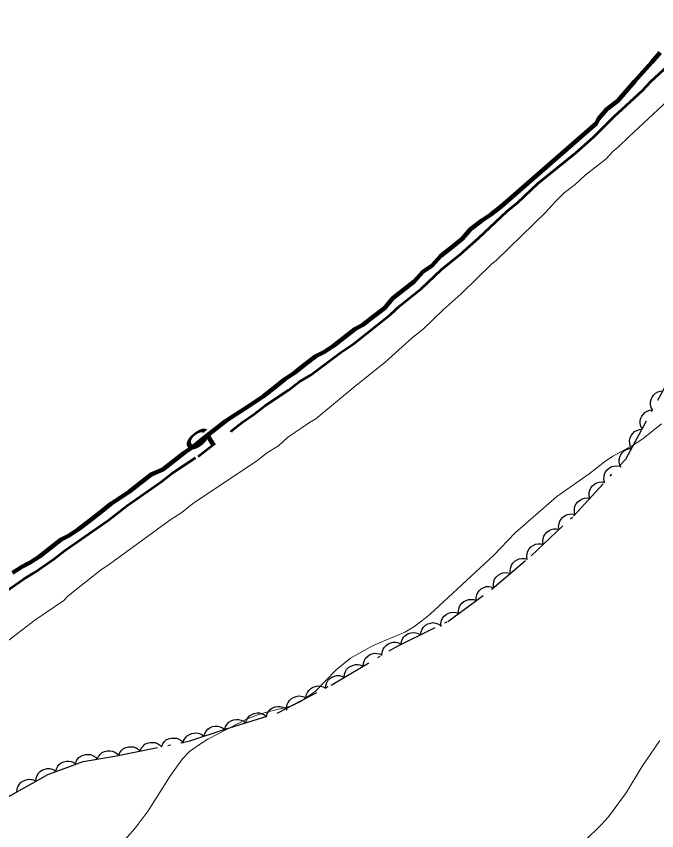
# Model space of a CAD drawing. Extents: x 355726 to 357533, y 5103782 to 5105258.
# Drawn here: x 355865.5 to 355909.5, y 5104531.6 to 5104587.5 of the extents above; entities that cross this region are included whole.
import ezdxf
from ezdxf.enums import TextEntityAlignment as Align

# ---------------------------------------------------------------- set-up
doc = ezdxf.new("R2010")
doc.units = 0
doc.header["$LTSCALE"] = 0.6
for name, pattern in [('DASH_DOUBLE_DOT', [9.2, 5, -1.2, 0.3, -1.2, 0.3, -1.2]), ('DOT_DASHED', [7.7, 5, -1.2, 0.3, -1.2]), ('LONG_DASHED', [7.5, 6, -1.5])]:
    doc.linetypes.add(name, pattern=pattern)
for name, color, linetype, lineweight in [('1', 7, 'LONG_DASHED', 53), ('2', 7, 'LONG_DASHED', 13), ('4', 7, 'DASH_DOUBLE_DOT', 53), ('44', 7, 'Continuous', 25)]:
    doc.layers.add(name, color=color, linetype=linetype, lineweight=lineweight)

msp = doc.modelspace()

# ---------------------------------------------------------------- linework, layer by layer
at = {"layer": '1', "linetype": 'Continuous'}
for points in [[(355880.28, 5104559.03), (355880.32, 5104559.11), (355881.05, 5104559.69), (355881.87, 5104560.23), (355882.6, 5104560.8), (355884.22, 5104561.88), (355884.96, 5104562.46), (355885.72, 5104562.92), (355887.84, 5104564.5), (355888.65, 5104565.04), (355891.22, 5104567.07), (355891.88, 5104567.69), (355893.35, 5104568.85), (355894.71, 5104570.17), (355896.02, 5104571.22), (355897.25, 5104572.31), (355899.23, 5104574.18), (355899.97, 5104574.76), (355901.33, 5104576.08), (355903.94, 5104578.18), (355905.18, 5104579.28), (355906.58, 5104580.67), (355908.52, 5104582.46), (355909.06, 5104583.05), (355913.95, 5104587.55)], [(355841.16, 5104531.16), (355844.5, 5104533.84), (355845.27, 5104534.3), (355847.39, 5104535.88), (355848.89, 5104536.92), (355850.07, 5104537.94), (355851.58, 5104538.98), (355852.31, 5104539.56), (355855.27, 5104541.56), (355856, 5104542.14), (355857.42, 5104543.03), (355857.82, 5104543.2), (355863.78, 5104547.28), (355864.51, 5104547.86), (355866.02, 5104548.9), (355866.78, 5104549.36), (355868.12, 5104550.3), (355868.86, 5104550.88), (355871.86, 5104552.96), (355873.12, 5104553.93), (355875.48, 5104555.58), (355876.21, 5104556.16), (355877.84, 5104557.23)]]:
    msp.add_lwpolyline(points, dxfattribs=at)
at = {"layer": '2', "linetype": 'Continuous'}
for points in [[(355865.02, 5104544.71), (355866.81, 5104546.08), (355868.8, 5104547.44), (355869.09, 5104547.77), (355871.29, 5104549.5), (355871.94, 5104549.93), (355876.08, 5104552.95), (355876.89, 5104553.49), (355877.63, 5104554.07), (355882.04, 5104557.04), (355882.78, 5104557.61), (355883.54, 5104558.07), (355884.16, 5104558.62), (355885.66, 5104559.66), (355886.1, 5104559.91), (355888.8, 5104562.16), (355890.84, 5104563.79), (355892.73, 5104565.5), (355893.47, 5104566.08), (355894.83, 5104567.4), (355896.06, 5104568.49), (355898.12, 5104570.51), (355898.49, 5104570.8), (355901.91, 5104574.13), (355902.49, 5104574.79), (355903.15, 5104575.42), (355903.89, 5104575.99), (355904.55, 5104576.62), (355906.02, 5104577.77), (355906.51, 5104578.29), (355906.88, 5104578.58), (355907.58, 5104579.28), (355912.56, 5104583.92)], [(355907.84, 5104558.09), (355908.55, 5104558.54), (355909.83, 5104559.58)], [(355872.63, 5104530.63), (355873.68, 5104531.8), (355874.58, 5104533.01), (355876.11, 5104535.42), (355876.93, 5104536.57), (355877.43, 5104537.07), (355878.04, 5104537.51), (355878.67, 5104537.92), (355881.34, 5104539.29), (355881.97, 5104539.55), (355882.62, 5104539.75), (355884.47, 5104540.2), (355885.02, 5104540.48), (355886.07, 5104541.22), (355887.5, 5104542.67), (355888.47, 5104543.47), (355889.98, 5104544.32), (355892.26, 5104545.3), (355892.82, 5104545.63), (355893.38, 5104546.04), (355893.94, 5104546.51), (355898.29, 5104550.53), (355899.78, 5104552.08), (355902.08, 5104554.11), (355902.64, 5104554.57), (355904.85, 5104556.13), (355905.9, 5104556.97), (355906.48, 5104557.36), (355907.84, 5104558.09)]]:
    msp.add_lwpolyline(points, dxfattribs=at)
at = {"layer": '2'}
msp.add_lwpolyline([(355904.56, 5104530.95), (355905.69, 5104532.04), (355906.18, 5104532.59), (355907.4, 5104534.24), (355908.48, 5104536.01), (355909.7, 5104537.84)], dxfattribs=at)
at = {"layer": '4', "linetype": 'Continuous', "lineweight": 90}
msp.add_lwpolyline([(355909.73, 5104585.07), (355909.15, 5104584.41), (355908.57, 5104583.74), (355907.98, 5104583.08), (355907.4, 5104582.41), (355906.82, 5104581.75), (355906.08, 5104581.17), (355905.5, 5104580.5), (355905.33, 5104580.2), (355898.84, 5104574.52), (355898.1, 5104573.94), (355897.46, 5104573.51), (355896.72, 5104572.93), (355896.14, 5104572.26), (355895.4, 5104571.68), (355894.67, 5104571.1), (355894.08, 5104570.44), (355893.44, 5104570.01), (355892.85, 5104569.34), (355892.12, 5104568.77), (355891.38, 5104568.19), (355890.8, 5104567.52), (355890.06, 5104566.94), (355889.33, 5104566.36), (355888.77, 5104566.08), (355888.03, 5104565.5), (355887.3, 5104564.92), (355886.65, 5104564.5), (355886.09, 5104564.22), (355885.35, 5104563.64), (355884.62, 5104563.06), (355883.97, 5104562.63), (355883.23, 5104562.05), (355882.5, 5104561.47), (355881.85, 5104561.04), (355881.2, 5104560.61), (355880.55, 5104560.18), (355879.9, 5104559.76), (355879.17, 5104559.18), (355878.43, 5104558.6), (355877.7, 5104558.02), (355877.05, 5104557.59), (355876.32, 5104557.01), (355875.58, 5104556.43), (355874.78, 5104556.09), (355874.05, 5104555.51), (355873.31, 5104554.93), (355872.66, 5104554.5), (355872.02, 5104554.07), (355871.28, 5104553.49), (355870.55, 5104552.91), (355869.81, 5104552.34), (355869.16, 5104551.91), (355868.6, 5104551.63), (355867.87, 5104551.05), (355867.13, 5104550.47), (355866.48, 5104550.04), (355865.92, 5104549.76), (355865.27, 5104549.33)], dxfattribs=at)
at = {"layer": '44', "linetype": 'DOT_DASHED'}
msp.add_lwpolyline([(355860.59, 5104530.06), (355864.97, 5104533.95), (355867.59, 5104535.44), (355870.11, 5104536.39), (355872.29, 5104536.75), (355877.45, 5104537.8), (355879.88, 5104538.6), (355883.49, 5104539.73), (355887.14, 5104541.63), (355891.6, 5104544.26), (355895.16, 5104546.01), (355898.21, 5104548.25), (355900.87, 5104550.51), (355903.78, 5104553.23), (355907.37, 5104557.14), (355913.61, 5104568.61)], dxfattribs=at)
at = {"layer": '44'}
for points in [[(355909.21, 5104560.52), (355909.11, 5104560.7), (355909.08, 5104560.9), (355909.07, 5104561.07), (355909.11, 5104561.24), (355909.18, 5104561.41), (355909.3, 5104561.56), (355909.41, 5104561.68), (355909.57, 5104561.76), (355909.75, 5104561.82), (355909.93, 5104561.84)], [(355908.49, 5104559.2), (355908.4, 5104559.39), (355908.36, 5104559.59), (355908.35, 5104559.75), (355908.39, 5104559.92), (355908.47, 5104560.09), (355908.58, 5104560.24), (355908.7, 5104560.36), (355908.85, 5104560.44), (355909.03, 5104560.5), (355909.21, 5104560.52)], [(355907.77, 5104557.88), (355907.68, 5104558.07), (355907.64, 5104558.27), (355907.63, 5104558.43), (355907.68, 5104558.6), (355907.75, 5104558.77), (355907.87, 5104558.92), (355907.98, 5104559.04), (355908.14, 5104559.12), (355908.31, 5104559.18), (355908.49, 5104559.2)], [(355907.06, 5104556.57), (355906.96, 5104556.75), (355906.92, 5104556.95), (355906.92, 5104557.12), (355906.96, 5104557.29), (355907.03, 5104557.46), (355907.15, 5104557.61), (355907.26, 5104557.72), (355907.42, 5104557.81), (355907.6, 5104557.87), (355907.77, 5104557.88)], [(355905.91, 5104555.55), (355905.87, 5104555.76), (355905.88, 5104555.96), (355905.91, 5104556.12), (355905.99, 5104556.28), (355906.1, 5104556.42), (355906.26, 5104556.54), (355906.39, 5104556.63), (355906.57, 5104556.67), (355906.75, 5104556.69), (355906.93, 5104556.66)], [(355904.9, 5104554.45), (355904.85, 5104554.65), (355904.86, 5104554.86), (355904.9, 5104555.02), (355904.98, 5104555.17), (355905.09, 5104555.32), (355905.24, 5104555.44), (355905.38, 5104555.52), (355905.55, 5104555.57), (355905.74, 5104555.58), (355905.91, 5104555.55)], [(355903.88, 5104553.34), (355903.84, 5104553.55), (355903.85, 5104553.75), (355903.88, 5104553.91), (355903.96, 5104554.07), (355904.08, 5104554.21), (355904.23, 5104554.33), (355904.37, 5104554.42), (355904.54, 5104554.46), (355904.72, 5104554.48), (355904.9, 5104554.45)], [(355902.8, 5104552.31), (355902.76, 5104552.52), (355902.79, 5104552.72), (355902.84, 5104552.88), (355902.93, 5104553.03), (355903.05, 5104553.16), (355903.21, 5104553.27), (355903.36, 5104553.35), (355903.53, 5104553.37), (355903.72, 5104553.38), (355903.89, 5104553.34)], [(355901.7, 5104551.29), (355901.67, 5104551.49), (355901.7, 5104551.69), (355901.74, 5104551.85), (355901.83, 5104552), (355901.96, 5104552.14), (355902.12, 5104552.25), (355902.26, 5104552.32), (355902.44, 5104552.35), (355902.62, 5104552.35), (355902.8, 5104552.31)], [(355900.61, 5104550.26), (355900.57, 5104550.47), (355900.6, 5104550.67), (355900.65, 5104550.83), (355900.74, 5104550.98), (355900.86, 5104551.12), (355901.02, 5104551.22), (355901.17, 5104551.3), (355901.34, 5104551.33), (355901.53, 5104551.33), (355901.7, 5104551.29)], [(355899.45, 5104549.3), (355899.43, 5104549.51), (355899.47, 5104549.71), (355899.52, 5104549.87), (355899.62, 5104550.01), (355899.75, 5104550.14), (355899.91, 5104550.24), (355900.06, 5104550.31), (355900.24, 5104550.33), (355900.42, 5104550.32), (355900.59, 5104550.28)], [(355898.31, 5104548.33), (355898.29, 5104548.54), (355898.32, 5104548.74), (355898.37, 5104548.9), (355898.47, 5104549.04), (355898.6, 5104549.17), (355898.77, 5104549.27), (355898.92, 5104549.34), (355899.09, 5104549.36), (355899.28, 5104549.35), (355899.45, 5104549.3)], [(355897.1, 5104547.44), (355897.1, 5104547.65), (355897.15, 5104547.84), (355897.21, 5104548), (355897.32, 5104548.13), (355897.46, 5104548.26), (355897.63, 5104548.34), (355897.78, 5104548.4), (355897.96, 5104548.41), (355898.14, 5104548.39), (355898.31, 5104548.33)], [(355895.9, 5104546.55), (355895.89, 5104546.76), (355895.94, 5104546.96), (355896, 5104547.11), (355896.11, 5104547.25), (355896.25, 5104547.37), (355896.42, 5104547.45), (355896.57, 5104547.51), (355896.75, 5104547.52), (355896.94, 5104547.5), (355897.1, 5104547.44)], [(355894.69, 5104545.66), (355894.68, 5104545.87), (355894.73, 5104546.07), (355894.79, 5104546.22), (355894.9, 5104546.36), (355895.04, 5104546.48), (355895.21, 5104546.57), (355895.37, 5104546.62), (355895.54, 5104546.63), (355895.73, 5104546.61), (355895.9, 5104546.55)], [(355893.29, 5104545.09), (355893.32, 5104545.3), (355893.4, 5104545.48), (355893.49, 5104545.62), (355893.62, 5104545.74), (355893.78, 5104545.83), (355893.96, 5104545.89), (355894.12, 5104545.92), (355894.3, 5104545.89), (355894.48, 5104545.84), (355894.63, 5104545.75)], [(355891.94, 5104544.43), (355891.97, 5104544.63), (355892.05, 5104544.82), (355892.14, 5104544.96), (355892.28, 5104545.07), (355892.43, 5104545.17), (355892.62, 5104545.22), (355892.78, 5104545.25), (355892.95, 5104545.23), (355893.13, 5104545.18), (355893.29, 5104545.09)], [(355890.63, 5104543.69), (355890.65, 5104543.9), (355890.72, 5104544.09), (355890.8, 5104544.24), (355890.92, 5104544.36), (355891.07, 5104544.47), (355891.25, 5104544.54), (355891.41, 5104544.58), (355891.58, 5104544.57), (355891.76, 5104544.53), (355891.93, 5104544.45)], [(355889.34, 5104542.93), (355889.36, 5104543.14), (355889.43, 5104543.33), (355889.5, 5104543.47), (355889.63, 5104543.6), (355889.78, 5104543.71), (355889.96, 5104543.77), (355890.12, 5104543.82), (355890.29, 5104543.81), (355890.47, 5104543.77), (355890.63, 5104543.69)], [(355888.05, 5104542.17), (355888.06, 5104542.38), (355888.13, 5104542.57), (355888.21, 5104542.71), (355888.34, 5104542.84), (355888.49, 5104542.94), (355888.67, 5104543.01), (355888.82, 5104543.05), (355889, 5104543.05), (355889.18, 5104543.01), (355889.34, 5104542.93)], [(355886.76, 5104541.41), (355886.77, 5104541.61), (355886.84, 5104541.8), (355886.92, 5104541.95), (355887.04, 5104542.07), (355887.19, 5104542.18), (355887.37, 5104542.25), (355887.53, 5104542.29), (355887.71, 5104542.28), (355887.89, 5104542.24), (355888.05, 5104542.17)], [(355885.42, 5104540.73), (355885.44, 5104540.94), (355885.52, 5104541.13), (355885.61, 5104541.27), (355885.74, 5104541.39), (355885.89, 5104541.49), (355886.08, 5104541.54), (355886.23, 5104541.58), (355886.41, 5104541.56), (355886.59, 5104541.51), (355886.75, 5104541.43)], [(355884.09, 5104540.04), (355884.11, 5104540.25), (355884.19, 5104540.43), (355884.28, 5104540.58), (355884.41, 5104540.69), (355884.56, 5104540.79), (355884.74, 5104540.85), (355884.9, 5104540.89), (355885.08, 5104540.87), (355885.26, 5104540.82), (355885.42, 5104540.73)], [(355881.27, 5104539.03), (355881.33, 5104539.23), (355881.44, 5104539.4), (355881.55, 5104539.53), (355881.7, 5104539.62), (355881.87, 5104539.69), (355882.06, 5104539.72), (355882.22, 5104539.72), (355882.39, 5104539.67), (355882.56, 5104539.59), (355882.7, 5104539.48)], [(355882.7, 5104539.48), (355882.76, 5104539.68), (355882.87, 5104539.85), (355882.98, 5104539.98), (355883.13, 5104540.07), (355883.3, 5104540.14), (355883.49, 5104540.17), (355883.65, 5104540.17), (355883.82, 5104540.12), (355883.99, 5104540.04), (355884.13, 5104539.93)], [(355879.84, 5104538.59), (355879.9, 5104538.79), (355880.01, 5104538.96), (355880.12, 5104539.08), (355880.27, 5104539.17), (355880.44, 5104539.24), (355880.63, 5104539.27), (355880.79, 5104539.27), (355880.96, 5104539.23), (355881.13, 5104539.15), (355881.27, 5104539.03)], [(355878.41, 5104538.12), (355878.47, 5104538.32), (355878.58, 5104538.49), (355878.69, 5104538.61), (355878.83, 5104538.71), (355879, 5104538.78), (355879.19, 5104538.81), (355879.36, 5104538.82), (355879.53, 5104538.77), (355879.69, 5104538.7), (355879.84, 5104538.59)], [(355875.5, 5104537.4), (355875.58, 5104537.6), (355875.71, 5104537.75), (355875.83, 5104537.87), (355875.99, 5104537.94), (355876.17, 5104538), (355876.36, 5104538), (355876.52, 5104537.99), (355876.69, 5104537.93), (355876.84, 5104537.83), (355876.97, 5104537.7)], [(355876.99, 5104537.65), (355877.04, 5104537.85), (355877.15, 5104538.02), (355877.26, 5104538.15), (355877.41, 5104538.24), (355877.58, 5104538.31), (355877.77, 5104538.34), (355877.93, 5104538.35), (355878.1, 5104538.3), (355878.27, 5104538.23), (355878.41, 5104538.12)], [(355872.56, 5104536.81), (355872.64, 5104537), (355872.77, 5104537.16), (355872.89, 5104537.27), (355873.05, 5104537.35), (355873.23, 5104537.4), (355873.42, 5104537.4), (355873.58, 5104537.39), (355873.75, 5104537.33), (355873.9, 5104537.23), (355874.03, 5104537.1)], [(355874.03, 5104537.1), (355874.11, 5104537.3), (355874.24, 5104537.45), (355874.36, 5104537.57), (355874.52, 5104537.64), (355874.7, 5104537.7), (355874.89, 5104537.7), (355875.05, 5104537.69), (355875.22, 5104537.63), (355875.37, 5104537.53), (355875.5, 5104537.4)], [(355869.61, 5104536.31), (355869.69, 5104536.5), (355869.83, 5104536.65), (355869.95, 5104536.76), (355870.11, 5104536.83), (355870.29, 5104536.87), (355870.48, 5104536.87), (355870.65, 5104536.86), (355870.81, 5104536.78), (355870.96, 5104536.68), (355871.09, 5104536.55)], [(355871.09, 5104536.55), (355871.17, 5104536.74), (355871.31, 5104536.89), (355871.43, 5104537), (355871.59, 5104537.07), (355871.77, 5104537.12), (355871.96, 5104537.12), (355872.13, 5104537.1), (355872.29, 5104537.03), (355872.44, 5104536.93), (355872.57, 5104536.8)], [(355868.23, 5104535.68), (355868.28, 5104535.88), (355868.38, 5104536.06), (355868.48, 5104536.19), (355868.62, 5104536.29), (355868.79, 5104536.37), (355868.98, 5104536.41), (355869.14, 5104536.42), (355869.31, 5104536.38), (355869.48, 5104536.31), (355869.63, 5104536.21)], [(355866.88, 5104535.04), (355866.89, 5104535.24), (355866.97, 5104535.43), (355867.05, 5104535.58), (355867.17, 5104535.7), (355867.33, 5104535.81), (355867.51, 5104535.87), (355867.66, 5104535.91), (355867.84, 5104535.9), (355868.02, 5104535.86), (355868.18, 5104535.78)], [(355865.57, 5104534.29), (355865.59, 5104534.5), (355865.66, 5104534.69), (355865.75, 5104534.84), (355865.87, 5104534.96), (355866.02, 5104535.06), (355866.2, 5104535.13), (355866.36, 5104535.17), (355866.54, 5104535.16), (355866.72, 5104535.12), (355866.88, 5104535.04)]]:
    msp.add_lwpolyline(points, dxfattribs=at)

# ---------------------------------------------------------------- texts
at = {"layer": '1', "width": 1.9}
msp.add_text('5', height=1.5, rotation=217.884, dxfattribs=at).set_placement((355877.72, 5104558.889), align=Align.CENTER)

doc.saveas('drawing.dxf')
